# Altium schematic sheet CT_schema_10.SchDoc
size 391 x 238 mm
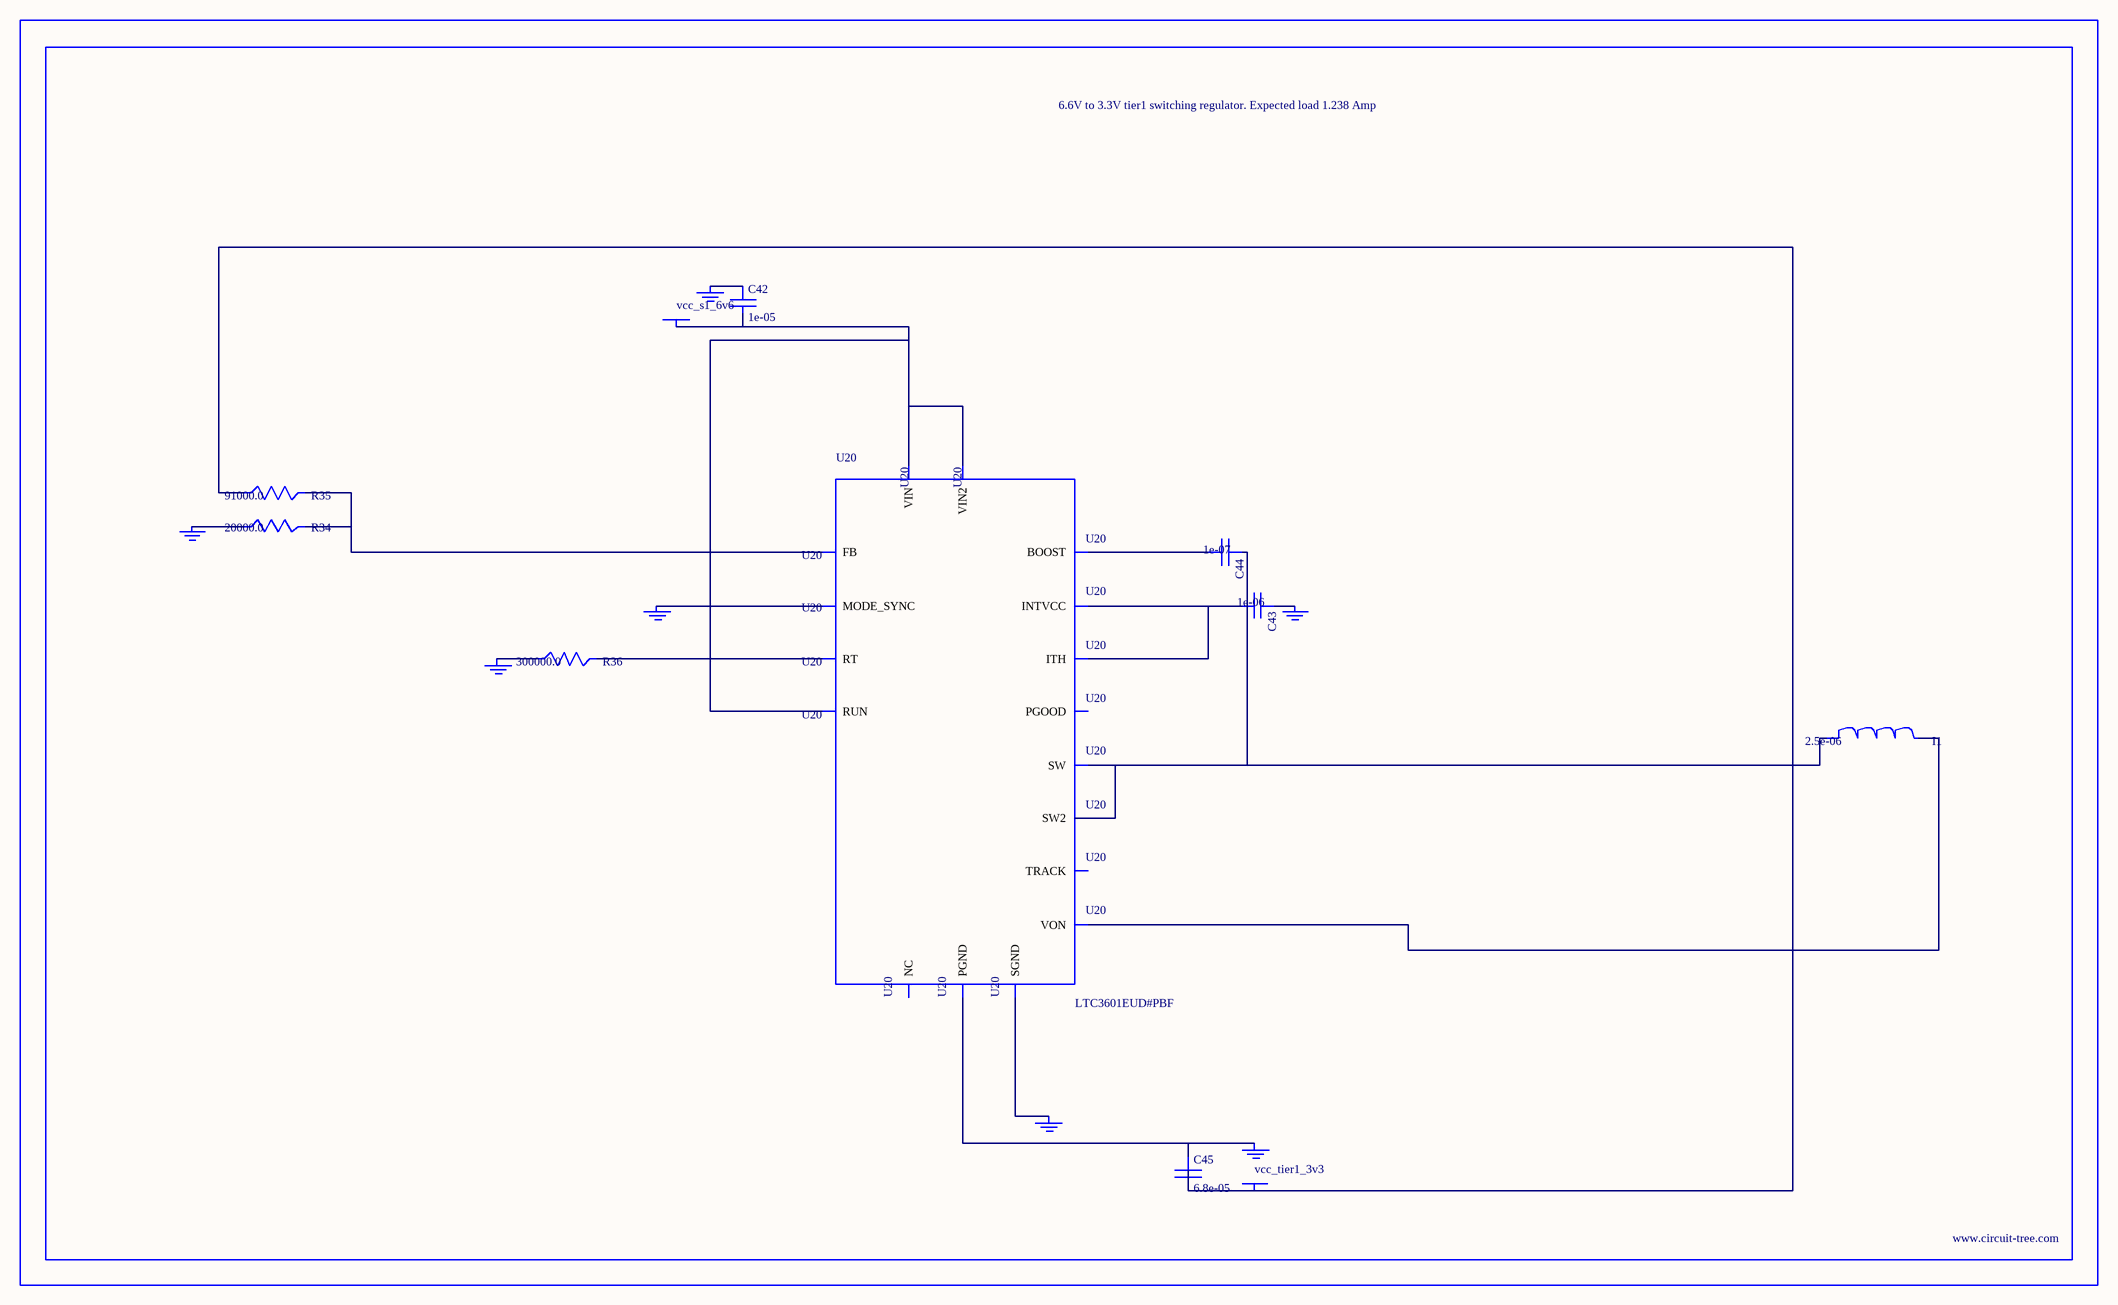
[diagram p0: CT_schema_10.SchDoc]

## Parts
BORDER9  (no value)
C42  1e-05  [C0805]
C43  1e-06  [C0603]
C44  1e-07  [C0402]
C45  6.8e-05  [2220]
GND_INSTANCE_9_0  (no value)
GND_INSTANCE_9_1  (no value)
GND_INSTANCE_9_2  (no value)
GND_INSTANCE_9_3  (no value)
GND_INSTANCE_9_4  (no value)
GND_INSTANCE_9_5  (no value)
GND_INSTANCE_9_6  (no value)
I1  2.5e-06  [DR1040]
POWER_INSTANCE_9_0  vcc_s1_6v6
POWER_INSTANCE_9_1  vcc_tier1_3v3
R34  20000.0  [R0603]
R35  91000.0  [R0603]
R36  300000.0  [R0603]
U20  LTC3601EUD#PBF  [QFN-16_EP]

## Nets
NetC42_1: C42.1 GND_INSTANCE_9_5.0(GND)
NetC42_2: C42.2 POWER_INSTANCE_9_0.0(PWR) U20.14(RUN) U20.15(VIN) U20.16(VIN2)
NetC43_1: C43.1 GND_INSTANCE_9_1.0(GND)
NetC43_2: C43.2 U20.7(INTVCC) U20.12(ITH)
NetC44_1: C44.1 I1.1 U20.3(SW) U20.4(SW2)
NetC44_2: C44.2 U20.6(BOOST)
NetC45_1: C45.1 GND_INSTANCE_9_6.0(GND) U20.17(PGND)
NetC45_2: C45.2 I1.2 POWER_INSTANCE_9_1.0(PWR) R35.1 U20.8(VON)
NetGND_INSTANCE_9_0_0: GND_INSTANCE_9_0.0(GND) U20.1(MODE_SYNC)
NetGND_INSTANCE_9_2_0: GND_INSTANCE_9_2.0(GND) U20.9(SGND)
NetGND_INSTANCE_9_3_0: GND_INSTANCE_9_3.0(GND) R36.1
NetGND_INSTANCE_9_4_0: GND_INSTANCE_9_4.0(GND) R34.1
NetR34_2: R34.2 R35.2 U20.11(FB)
NetR36_2: R36.2 U20.10(RT)

Not connected (* = marked no-connect by the designer): U20 2(PGOOD) 5(NC) 13(TRACK)

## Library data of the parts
BORDER9 = BORDER_PAGE9
C42 = C0805C106K8RACTU
C43 = C0603C105K3RACTU
C44 = C0402C104K3RACTU
C45 = C5750X5R1A686M
GND_INSTANCE_9_0-GND_INSTANCE_9_6 = GND
I1 = DR1040-2R5-R
POWER_INSTANCE_9_0 POWER_INSTANCE_9_1 = PWR
R34 = RC0603JR-0720KL
R35 = RC0603JR-0791KL
R36 = RC0603JR-07300KL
